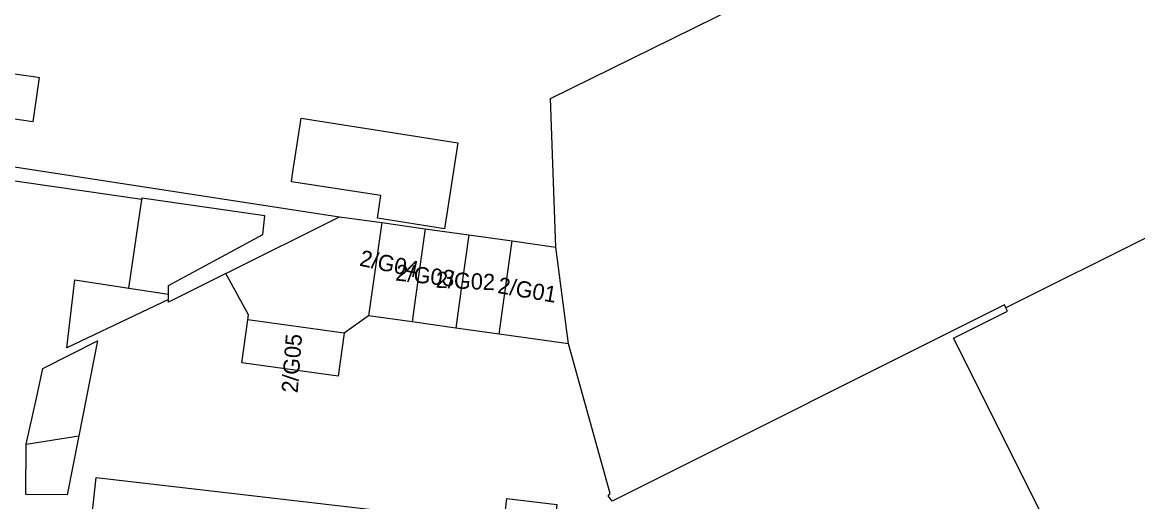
# Model space of a CAD drawing. Extents: x 162250 to 162654, y 380744 to 381605.
# Drawn here: x 162353.5 to 162422.3, y 381381.7 to 381411.4 of the extents above; entities that cross this region are included whole.
import ezdxf

# ---------------------------------------------------------------- set-up
doc = ezdxf.new("R2010")
doc.units = 0
for name, color, linetype in [('IMGEO_Pand', 7, 'Continuous'), ('IMGEO_Pand_nummerreeks', 7, 'Continuous'), ('IMGEO_Voetpad_open', 7, 'Continuous')]:
    doc.layers.add(name, color=color, linetype=linetype)

msp = doc.modelspace()

# ---------------------------------------------------------------- linework, layer by layer
at = {"layer": 'IMGEO_Pand'}
for points in [[(162386.424, 381397.47), (162386.104, 381406.654), (162398.76, 381412.894), (162398.377, 381413.769)], [(162444.781, 381408.746), (162432.355, 381402.775), (162414.2, 381393.719)], [(162352.555, 381408.238), (162354.32, 381407.98), (162354.536, 381407.946), (162354.13, 381405.202), (162347.377, 381406.2), (162346.955, 381403.343)], [(162380.384, 381403.915), (162379.556, 381398.605), (162375.406, 381399.252), (162375.625, 381400.647), (162370.099, 381401.509), (162370.151, 381401.84), (162370.71, 381405.424), (162380.384, 381403.915)], [(162360.063, 381394.93), (162360.858, 381400.414)], [(162362.518, 381394.554), (162362.518, 381395.093), (162365.555, 381396.74), (162368.328, 381398.244), (162368.468, 381399.398), (162360.87, 381400.499), (162360.858, 381400.414)], [(162366.054, 381395.832), (162373.077, 381399.345)], [(162373.077, 381399.345), (162375.677, 381398.98)], [(162375.677, 381398.98), (162374.868, 381393.224)], [(162375.677, 381398.98), (162378.363, 381398.602)], [(162378.363, 381398.602), (162377.75, 381394.237), (162377.555, 381392.847)], [(162378.363, 381398.602), (162381.05, 381398.225)], [(162381.05, 381398.225), (162380.434, 381393.84), (162380.242, 381392.469)], [(162381.05, 381398.225), (162383.737, 381397.847)], [(162382.929, 381392.092), (162383.118, 381393.443), (162383.737, 381397.847)], [(162383.737, 381397.847), (162386.424, 381397.47)], [(162387.21, 381391.49), (162386.424, 381397.47)], [(162362.518, 381394.226), (162356.246, 381391.25), (162356.733, 381395.44), (162360.063, 381394.93)], [(162367.413, 381392.985), (162367.455, 381393.281), (162366.054, 381395.832)], [(162360.063, 381394.93), (162362.518, 381394.554)], [(162362.518, 381394.226), (162362.518, 381394.554)], [(162414.2, 381393.719), (162414.112, 381393.895), (162389.894, 381381.787), (162389.657, 381382.11), (162389.779, 381382.259), (162387.21, 381391.49)], [(162418.11, 381377.574), (162410.971, 381391.853), (162414.301, 381393.518), (162414.2, 381393.719)], [(162373.357, 381392.15), (162372.984, 381389.492), (162367.04, 381390.327), (162367.413, 381392.985)], [(162373.357, 381392.15), (162367.413, 381392.985)], [(162374.868, 381393.224), (162373.357, 381392.15)], [(162377.555, 381392.847), (162374.868, 381393.224)], [(162380.242, 381392.469), (162377.555, 381392.847)], [(162382.929, 381392.092), (162380.242, 381392.469)], [(162387.21, 381391.49), (162382.929, 381392.092)], [(162353.72, 381385.307), (162354.36, 381388.13), (162354.752, 381389.967), (162358.135, 381391.689), (162356.982, 381385.822)], [(162356.982, 381385.822), (162356.26, 381382.172), (162353.699, 381382.181), (162353.72, 381385.307)], [(162353.72, 381385.307), (162356.982, 381385.822)], [(162383.213, 381380.328), (162383.399, 381381.936), (162386.494, 381381.578), (162386.433, 381381.044), (162385.86, 381376.076), (162383.142, 381376.39), (162382.714, 381372.677), (162376.33, 381373.414), (162369.947, 381374.15), (162363.564, 381374.886), (162357.18, 381375.623), (162357.754, 381380.59), (162358.038, 381383.231), (162364.441, 381382.493), (162370.825, 381381.757), (162377.208, 381381.02), (162383.213, 381380.328)]]:
    msp.add_lwpolyline(points, dxfattribs=at)
at = {"layer": 'IMGEO_Voetpad_open'}
for points in [[(162346.955, 381403.343), (162373.077, 381399.345)], [(162360.858, 381400.414), (162351.59, 381401.756)], [(162366.054, 381395.832), (162362.518, 381394.063), (162362.518, 381394.226)]]:
    msp.add_lwpolyline(points, dxfattribs=at)

# ---------------------------------------------------------------- texts
at = {"layer": 'IMGEO_Pand_nummerreeks'}
for s, rotation, p in [('2/G04', 348.23171, (162374.256, 381396.327)), ('2/G03', 353.8845, (162376.497, 381395.412)), ('2/G02', 357.51045, (162379.003, 381394.961)), ('2/G01', 350.31121, (162382.785, 381394.638)), ('2/G05', 85.60129, (162370.485, 381388.435))]:
    msp.add_text(s, height=1, rotation=rotation, dxfattribs=at).set_placement(p)

doc.saveas('drawing.dxf')
